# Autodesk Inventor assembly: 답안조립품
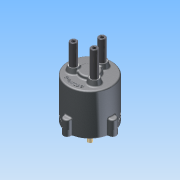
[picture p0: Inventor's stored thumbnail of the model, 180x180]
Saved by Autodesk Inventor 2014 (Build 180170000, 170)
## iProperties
Created: 2015-09
Part Number: 답안조립품
Document SubType Name: Assembly
Designer: study
Author: study
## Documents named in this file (11)
- C:\Users\study\Desktop\350916V1012\답안조립품.iam
- C:\Users\study\Desktop\350916V1012\몸체.ipt
- C:\Users\study\Desktop\350916V1012\판캠.ipt
- C:\Users\study\Desktop\350916V1012\베어링 NA 4900.ipt
- C:\Users\study\Desktop\350916V1012\메인 축.ipt
- C:\Users\study\Desktop\350916V1012\멈춤링 10 x 1.ipt
- C:\Users\study\Desktop\350916V1012\멈춤링 22 x 1.2.ipt
- C:\Users\study\Desktop\350916V1012\커버.ipt
- C:\Users\study\Desktop\350916V1012\오일실.ipt
- C:\Users\study\Desktop\350916V1012\슬라이드 축.ipt
- C:\Users\study\Desktop\350916V1012\M5x0.8x20.ipt
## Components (4 placed, 1 different names)
1. M5x0.8x20:1
2. M5x0.8x20:2
3. M5x0.8x20:3
4. M5x0.8x20:4
